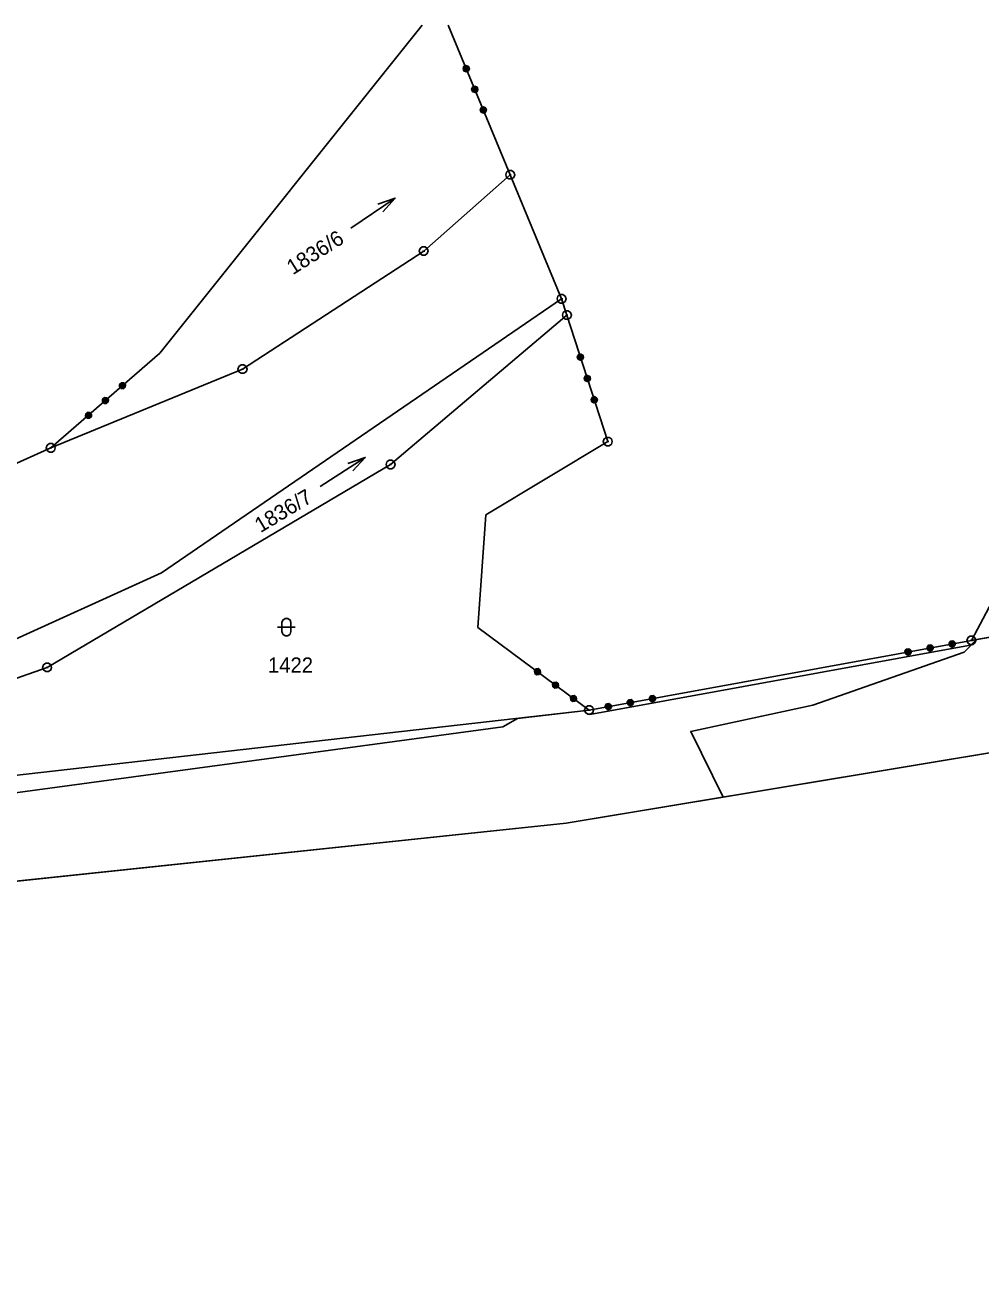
# Model space of a CAD drawing. Extents: x -779618 to -776429, y -1144546 to -1143350.
# Drawn here: x -778776.3 to -778669.3, y -1143491.2 to -1143349.7 of the extents above; entities that cross this region are included whole.
import ezdxf

# ---------------------------------------------------------------- set-up
doc = ezdxf.new("R2010")
doc.units = 0
for name, color, linetype in [('1', 7, 'Continuous'), ('11', 7, 'Continuous'), ('2', 7, 'Continuous'), ('3', 7, 'Continuous'), ('4', 7, 'Continuous'), ('8', 7, 'Continuous')]:
    doc.layers.add(name, color=color, linetype=linetype)

msp = doc.modelspace()

# ---------------------------------------------------------------- linework, layer by layer
at = {"layer": '1'}
for p, q in [((-778731.85, -1143349.66), (-778761.21, -1143386.36)), ((-778728.92, -1143349.66), (-778721.98, -1143366.4)), ((-778731.67, -1143374.93), (-778721.98, -1143366.4)), ((-778716.22, -1143380.29), (-778721.98, -1143366.4)), ((-778751.96, -1143388.16), (-778731.67, -1143374.93)), ((-778716.22, -1143380.29), (-778761.03, -1143410.96)), ((-778715.63, -1143382.11), (-778716.22, -1143380.29)), ((-778735.38, -1143398.84), (-778715.63, -1143382.11)), ((-778715.63, -1143382.11), (-778711.05, -1143396.27)), ((-778773.43, -1143396.97), (-778761.21, -1143386.36)), ((-778773.43, -1143396.97), (-778751.96, -1143388.16)), ((-778724.72, -1143404.47), (-778711.05, -1143396.27)), ((-778773.43, -1143396.97), (-778780.4, -1143400.1)), ((-778773.85, -1143421.55), (-778735.38, -1143398.84)), ((-778725.59, -1143417.09), (-778724.72, -1143404.47)), ((-778592.85, -1143405), (-778670.33, -1143418.53)), ((-778664.27, -1143407.08), (-778670.33, -1143418.53)), ((-778761.03, -1143410.96), (-778822.71, -1143438.81)), ((-778713.14, -1143426.33), (-778725.59, -1143417.09)), ((-778715.72, -1143438.98), (-778589.94, -1143418.07)), ((-778670.33, -1143418.53), (-778713.14, -1143426.33)), ((-778822.71, -1143438.81), (-778773.85, -1143421.55)), ((-778822.71, -1143438.81), (-778713.14, -1143426.33)), ((-778818.52, -1143449.84), (-778715.72, -1143438.98))]:
    msp.add_line(p, q, dxfattribs=at)
for points in [[(-778726.56, -1143354.51), (-778726.66, -1143354.76), (-778726.91, -1143354.86), (-778727.16, -1143354.76), (-778727.26, -1143354.51), (-778727.16, -1143354.26), (-778726.91, -1143354.16), (-778726.66, -1143354.26), (-778726.56, -1143354.51), (-778726.59, -1143354.53), (-778726.69, -1143354.31), (-778726.79, -1143354.27), (-778726.64, -1143354.64), (-778726.69, -1143354.72), (-778726.9, -1143354.22), (-778726.97, -1143354.25), (-778726.77, -1143354.74), (-778726.84, -1143354.78), (-778727.04, -1143354.29), (-778727.11, -1143354.33), (-778726.91, -1143354.81), (-778727, -1143354.8), (-778727.17, -1143354.4), (-778727.21, -1143354.5), (-778727.11, -1143354.76)], [(-778725.6, -1143356.83), (-778725.7, -1143357.08), (-778725.95, -1143357.18), (-778726.2, -1143357.08), (-778726.3, -1143356.83), (-778726.2, -1143356.58), (-778725.95, -1143356.47), (-778725.7, -1143356.58), (-778725.6, -1143356.83), (-778725.64, -1143356.83), (-778725.73, -1143356.61), (-778725.84, -1143356.57), (-778725.68, -1143356.94), (-778725.73, -1143357.04), (-778725.94, -1143356.52), (-778726.02, -1143356.56), (-778725.8, -1143357.07), (-778725.88, -1143357.1), (-778726.09, -1143356.59), (-778726.16, -1143356.62), (-778725.95, -1143357.13), (-778726.05, -1143357.09), (-778726.21, -1143356.72), (-778726.25, -1143356.83), (-778726.16, -1143357.05)], [(-778724.64, -1143359.15), (-778724.74, -1143359.39), (-778724.99, -1143359.5), (-778725.24, -1143359.39), (-778725.34, -1143359.15), (-778725.24, -1143358.9), (-778724.99, -1143358.79), (-778724.74, -1143358.9), (-778724.64, -1143359.15), (-778724.69, -1143359.12), (-778724.78, -1143358.9), (-778724.88, -1143358.88), (-778724.74, -1143359.23), (-778724.78, -1143359.33), (-778724.98, -1143358.85), (-778725.05, -1143358.88), (-778724.85, -1143359.36), (-778724.93, -1143359.39), (-778725.13, -1143358.91), (-778725.2, -1143358.94), (-778725, -1143359.42), (-778725.09, -1143359.41), (-778725.25, -1143359.03), (-778725.31, -1143359.11), (-778725.21, -1143359.33)], [(-778713.76, -1143386.84), (-778713.89, -1143387.08), (-778714.14, -1143387.16), (-778714.38, -1143387.04), (-778714.47, -1143386.78), (-778714.34, -1143386.54), (-778714.09, -1143386.46), (-778713.85, -1143386.58), (-778713.76, -1143386.84), (-778713.8, -1143386.86), (-778713.87, -1143386.63), (-778713.97, -1143386.58), (-778713.85, -1143386.96), (-778713.91, -1143387.04), (-778714.07, -1143386.53), (-778714.15, -1143386.55), (-778713.99, -1143387.06), (-778714.06, -1143387.09), (-778714.22, -1143386.59), (-778714.3, -1143386.61), (-778714.14, -1143387.11), (-778714.23, -1143387.09), (-778714.36, -1143386.68), (-778714.42, -1143386.77), (-778714.33, -1143387.04)], [(-778712.99, -1143389.22), (-778713.11, -1143389.46), (-778713.37, -1143389.55), (-778713.61, -1143389.42), (-778713.69, -1143389.17), (-778713.57, -1143388.93), (-778713.31, -1143388.85), (-778713.08, -1143388.97), (-778712.99, -1143389.22), (-778713.03, -1143389.23), (-778713.11, -1143389), (-778713.21, -1143388.95), (-778713.09, -1143389.33), (-778713.14, -1143389.43), (-778713.31, -1143388.9), (-778713.38, -1143388.92), (-778713.21, -1143389.45), (-778713.29, -1143389.48), (-778713.46, -1143388.95), (-778713.54, -1143388.97), (-778713.36, -1143389.5), (-778713.47, -1143389.45), (-778713.59, -1143389.07), (-778713.64, -1143389.17), (-778713.57, -1143389.4)], [(-778765.53, -1143389.69), (-778765.26, -1143389.7), (-778765.08, -1143389.91), (-778765.1, -1143390.18), (-778765.31, -1143390.35), (-778765.57, -1143390.33), (-778765.75, -1143390.13), (-778765.73, -1143389.86), (-778765.53, -1143389.69), (-778765.53, -1143389.74), (-778765.71, -1143389.9), (-778765.71, -1143390), (-778765.42, -1143389.75), (-778765.31, -1143389.76), (-778765.7, -1143390.1), (-778765.65, -1143390.16), (-778765.25, -1143389.82), (-778765.2, -1143389.88), (-778765.59, -1143390.22), (-778765.55, -1143390.29), (-778765.16, -1143389.95), (-778765.14, -1143390.03), (-778765.44, -1143390.3), (-778765.35, -1143390.33), (-778765.17, -1143390.17)], [(-778767.42, -1143391.33), (-778767.16, -1143391.35), (-778766.98, -1143391.55), (-778767, -1143391.82), (-778767.2, -1143392), (-778767.47, -1143391.98), (-778767.65, -1143391.78), (-778767.63, -1143391.51), (-778767.42, -1143391.33), (-778767.41, -1143391.37), (-778767.59, -1143391.53), (-778767.59, -1143391.64), (-778767.29, -1143391.38), (-778767.18, -1143391.38), (-778767.6, -1143391.75), (-778767.55, -1143391.81), (-778767.13, -1143391.44), (-778767.07, -1143391.51), (-778767.5, -1143391.87), (-778767.45, -1143391.93), (-778767.02, -1143391.57), (-778767.03, -1143391.68), (-778767.33, -1143391.94), (-778767.22, -1143391.95), (-778767.04, -1143391.79)], [(-778712.22, -1143391.61), (-778712.34, -1143391.85), (-778712.6, -1143391.94), (-778712.84, -1143391.81), (-778712.92, -1143391.56), (-778712.8, -1143391.32), (-778712.54, -1143391.23), (-778712.3, -1143391.36), (-778712.22, -1143391.61), (-778712.27, -1143391.59), (-778712.34, -1143391.36), (-778712.44, -1143391.33), (-778712.32, -1143391.69), (-778712.37, -1143391.79), (-778712.53, -1143391.29), (-778712.61, -1143391.32), (-778712.45, -1143391.81), (-778712.53, -1143391.84), (-778712.69, -1143391.34), (-778712.77, -1143391.36), (-778712.61, -1143391.85), (-778712.69, -1143391.84), (-778712.82, -1143391.45), (-778712.88, -1143391.52), (-778712.81, -1143391.75)], [(-778769.32, -1143392.98), (-778769.05, -1143393), (-778768.87, -1143393.2), (-778768.89, -1143393.47), (-778769.1, -1143393.65), (-778769.37, -1143393.63), (-778769.54, -1143393.42), (-778769.52, -1143393.15), (-778769.32, -1143392.98), (-778769.29, -1143393), (-778769.47, -1143393.16), (-778769.47, -1143393.27), (-778769.17, -1143393.01), (-778769.07, -1143393.03), (-778769.48, -1143393.38), (-778769.43, -1143393.44), (-778769.03, -1143393.1), (-778768.97, -1143393.15), (-778769.37, -1143393.5), (-778769.32, -1143393.56), (-778768.92, -1143393.21), (-778768.9, -1143393.3), (-778769.23, -1143393.59), (-778769.12, -1143393.6), (-778768.91, -1143393.42)], [(-778672.56, -1143419.26), (-778672.79, -1143419.11), (-778672.83, -1143418.84), (-778672.68, -1143418.62), (-778672.42, -1143418.57), (-778672.19, -1143418.73), (-778672.15, -1143418.99), (-778672.3, -1143419.21), (-778672.56, -1143419.26), (-778672.58, -1143419.22), (-778672.35, -1143419.18), (-778672.28, -1143419.09), (-778672.67, -1143419.16), (-778672.75, -1143419.09), (-778672.22, -1143419), (-778672.23, -1143418.92), (-778672.75, -1143419.01), (-778672.78, -1143418.93), (-778672.26, -1143418.84), (-778672.27, -1143418.76), (-778672.79, -1143418.86), (-778672.76, -1143418.77), (-778672.33, -1143418.69), (-778672.42, -1143418.63), (-778672.69, -1143418.68)], [(-778677.5, -1143420.16), (-778677.72, -1143420.01), (-778677.77, -1143419.74), (-778677.62, -1143419.52), (-778677.35, -1143419.47), (-778677.13, -1143419.63), (-778677.09, -1143419.89), (-778677.24, -1143420.11), (-778677.5, -1143420.16), (-778677.47, -1143420.12), (-778677.24, -1143420.07), (-778677.19, -1143419.98), (-778677.56, -1143420.05), (-778677.66, -1143419.99), (-778677.15, -1143419.89), (-778677.16, -1143419.82), (-778677.67, -1143419.91), (-778677.69, -1143419.83), (-778677.17, -1143419.74), (-778677.18, -1143419.66), (-778677.69, -1143419.75), (-778677.67, -1143419.66), (-778677.26, -1143419.59), (-778677.33, -1143419.52), (-778677.56, -1143419.56)], [(-778675.03, -1143419.71), (-778675.26, -1143419.56), (-778675.3, -1143419.29), (-778675.15, -1143419.07), (-778674.89, -1143419.02), (-778674.66, -1143419.18), (-778674.62, -1143419.44), (-778674.77, -1143419.66), (-778675.03, -1143419.71), (-778675.03, -1143419.67), (-778674.8, -1143419.63), (-778674.73, -1143419.54), (-778675.12, -1143419.61), (-778675.22, -1143419.54), (-778674.67, -1143419.44), (-778674.68, -1143419.36), (-778675.23, -1143419.46), (-778675.25, -1143419.39), (-778674.7, -1143419.28), (-778674.71, -1143419.21), (-778675.26, -1143419.31), (-778675.2, -1143419.21), (-778674.8, -1143419.14), (-778674.9, -1143419.08), (-778675.13, -1143419.12)], [(-778719.23, -1143422.21), (-778719.27, -1143421.94), (-778719.11, -1143421.72), (-778718.85, -1143421.68), (-778718.63, -1143421.85), (-778718.59, -1143422.11), (-778718.75, -1143422.33), (-778719.02, -1143422.37), (-778719.23, -1143422.21), (-778719.18, -1143422.2), (-778718.98, -1143422.34), (-778718.89, -1143422.31), (-778719.19, -1143422.09), (-778719.21, -1143421.97), (-778718.79, -1143422.28), (-778718.74, -1143422.22), (-778719.16, -1143421.91), (-778719.11, -1143421.85), (-778718.7, -1143422.16), (-778718.64, -1143422.1), (-778719.06, -1143421.79), (-778718.98, -1143421.75), (-778718.65, -1143421.99), (-778718.64, -1143421.9), (-778718.83, -1143421.75)], [(-778717.22, -1143423.7), (-778717.26, -1143423.44), (-778717.1, -1143423.22), (-778716.83, -1143423.18), (-778716.61, -1143423.34), (-778716.57, -1143423.61), (-778716.73, -1143423.82), (-778717, -1143423.86), (-778717.22, -1143423.7), (-778717.19, -1143423.68), (-778716.99, -1143423.82), (-778716.88, -1143423.8), (-778717.2, -1143423.56), (-778717.22, -1143423.45), (-778716.77, -1143423.79), (-778716.72, -1143423.72), (-778717.17, -1143423.39), (-778717.12, -1143423.32), (-778716.67, -1143423.66), (-778716.63, -1143423.59), (-778717.08, -1143423.26), (-778716.96, -1143423.24), (-778716.64, -1143423.48), (-778716.66, -1143423.37), (-778716.85, -1143423.23)], [(-778715.2, -1143425.2), (-778715.24, -1143424.93), (-778715.08, -1143424.72), (-778714.81, -1143424.68), (-778714.6, -1143424.84), (-778714.56, -1143425.1), (-778714.72, -1143425.32), (-778714.99, -1143425.36), (-778715.2, -1143425.2), (-778715.19, -1143425.16), (-778714.99, -1143425.3), (-778714.88, -1143425.29), (-778715.2, -1143425.05), (-778715.2, -1143424.95), (-778714.77, -1143425.27), (-778714.72, -1143425.21), (-778715.15, -1143424.89), (-778715.11, -1143424.82), (-778714.68, -1143425.14), (-778714.63, -1143425.07), (-778715.06, -1143424.76), (-778714.97, -1143424.72), (-778714.63, -1143424.98), (-778714.64, -1143424.87), (-778714.86, -1143424.7)], [(-778711.07, -1143426.28), (-778711.29, -1143426.12), (-778711.34, -1143425.86), (-778711.18, -1143425.64), (-778710.92, -1143425.59), (-778710.7, -1143425.74), (-778710.65, -1143426.01), (-778710.8, -1143426.23), (-778711.07, -1143426.28), (-778711.03, -1143426.23), (-778710.8, -1143426.19), (-778710.75, -1143426.1), (-778711.13, -1143426.17), (-778711.22, -1143426.1), (-778710.71, -1143426.01), (-778710.72, -1143425.93), (-778711.23, -1143426.02), (-778711.25, -1143425.95), (-778710.74, -1143425.85), (-778710.74, -1143425.77), (-778711.25, -1143425.86), (-778711.23, -1143425.78), (-778710.82, -1143425.71), (-778710.89, -1143425.64), (-778711.12, -1143425.68)], [(-778708.6, -1143425.83), (-778708.82, -1143425.67), (-778708.87, -1143425.41), (-778708.71, -1143425.19), (-778708.45, -1143425.14), (-778708.23, -1143425.29), (-778708.18, -1143425.56), (-778708.33, -1143425.78), (-778708.6, -1143425.83), (-778708.59, -1143425.79), (-778708.36, -1143425.74), (-778708.29, -1143425.65), (-778708.69, -1143425.72), (-778708.78, -1143425.66), (-778708.23, -1143425.56), (-778708.24, -1143425.48), (-778708.79, -1143425.58), (-778708.81, -1143425.5), (-778708.26, -1143425.4), (-778708.27, -1143425.32), (-778708.82, -1143425.42), (-778708.76, -1143425.33), (-778708.37, -1143425.26), (-778708.46, -1143425.19), (-778708.69, -1143425.24)], [(-778706.13, -1143425.38), (-778706.35, -1143425.22), (-778706.4, -1143424.96), (-778706.24, -1143424.74), (-778705.98, -1143424.69), (-778705.76, -1143424.84), (-778705.71, -1143425.11), (-778705.86, -1143425.33), (-778706.13, -1143425.38), (-778706.14, -1143425.34), (-778705.91, -1143425.3), (-778705.84, -1143425.2), (-778706.24, -1143425.28), (-778706.31, -1143425.21), (-778705.78, -1143425.11), (-778705.79, -1143425.03), (-778706.32, -1143425.13), (-778706.34, -1143425.05), (-778705.82, -1143424.95), (-778705.83, -1143424.88), (-778706.35, -1143424.97), (-778706.32, -1143424.88), (-778705.9, -1143424.81), (-778705.98, -1143424.74), (-778706.25, -1143424.79)]]:
    msp.add_lwpolyline(points, dxfattribs=at)
at = {"layer": '11'}
for p, q in [((-778713.14, -1143426.33), (-778670.33, -1143418.53)), ((-778670.33, -1143418.53), (-778669.74, -1143418.43))]:
    msp.add_line(p, q, dxfattribs=at)
for points in [[(-778654.99, -1143388.21), (-778601.22, -1143389.03), (-778529.9, -1143390.12), (-778475.97, -1143403.25), (-778476.13, -1143420.57), (-778501.66, -1143410.47), (-778538.84, -1143404.75), (-778592.85, -1143405), (-778669.74, -1143418.43)], [(-778698.13, -1143436.06), (-778701.77, -1143428.71), (-778688.08, -1143425.78), (-778671.14, -1143419.83), (-778669.74, -1143418.43)], [(-778391.62, -1143606.39), (-778385.54, -1143593.64), (-778391.52, -1143569.91), (-778391.96, -1143568.16), (-778423.5, -1143521.47), (-778427.52, -1143515.51), (-778428.85, -1143497.7), (-778426.9, -1143499.73), (-778427, -1143498.81), (-778429.76, -1143496.2), (-778458.56, -1143448.73), (-778464.32, -1143442.75), (-778464.56, -1143442.31), (-778464.82, -1143442.22), (-778468.65, -1143438.25), (-778504.96, -1143426.73), (-778540.55, -1143418.42), (-778589.94, -1143418.07), (-778698.13, -1143436.06)], [(-779127.81, -1143586.82), (-779123.49, -1143583.03), (-778998.42, -1143521.62), (-778865.4, -1143457.75), (-778880.7, -1143461.44), (-778864.23, -1143454.32), (-778822.71, -1143438.81), (-778812.34, -1143437.63), (-778812.03, -1143439.16), (-778787.11, -1143436.89), (-778722.82, -1143428.2), (-778721.18, -1143427.25), (-778713.14, -1143426.33)], [(-779126.05, -1143590.02), (-779014.28, -1143536.05), (-778904.07, -1143484.54), (-778858.15, -1143464.42), (-778818.52, -1143449.84), (-778715.72, -1143438.98), (-778698.13, -1143436.06)]]:
    msp.add_lwpolyline(points, dxfattribs=at)
at = {"layer": '3'}
for p, q in [((-778739.84, -1143372.36), (-778734.88, -1143369)), ((-778743.25, -1143401.28), (-778738.21, -1143398.04))]:
    msp.add_line(p, q, dxfattribs=at)
for points in [[(-778736.81, -1143369.7), (-778734.88, -1143369), (-778736.25, -1143370.53)], [(-778740.16, -1143398.7), (-778738.21, -1143398.04), (-778739.62, -1143399.54)], [(-778748.05, -1143417.03), (-778746.78, -1143417.03), (-778746.05, -1143417.03)]]:
    msp.add_lwpolyline(points, dxfattribs=at)
msp.add_lwpolyline([(-778747.55, -1143416.53), (-778747.45, -1143416.24), (-778747.2, -1143416.06), (-778746.89, -1143416.06), (-778746.64, -1143416.24), (-778746.54, -1143416.53), (-778746.54, -1143417.53), (-778746.64, -1143417.82), (-778746.89, -1143418), (-778747.2, -1143418), (-778747.45, -1143417.82), (-778747.55, -1143417.53)], close=True, dxfattribs=at)
at = {"layer": '4'}
msp.add_line((-778670.24, -1143419.02), (-778713.05, -1143426.82), dxfattribs=at)
at = {"layer": '8'}
for p, q in [((-778722.1, -1143366.4), (-778721.86, -1143366.4)), ((-778731.79, -1143374.93), (-778731.55, -1143374.93)), ((-778716.34, -1143380.29), (-778716.1, -1143380.29)), ((-778715.75, -1143382.11), (-778715.51, -1143382.11)), ((-778752.08, -1143388.16), (-778751.84, -1143388.16)), ((-778711.17, -1143396.27), (-778710.93, -1143396.27)), ((-778773.55, -1143396.97), (-778773.31, -1143396.97)), ((-778735.5, -1143398.84), (-778735.26, -1143398.84)), ((-778670.45, -1143418.53), (-778670.21, -1143418.53)), ((-778773.97, -1143421.55), (-778773.73, -1143421.55)), ((-778713.26, -1143426.33), (-778713.02, -1143426.33))]:
    msp.add_line(p, q, dxfattribs=at)
for points in [[(-778721.83, -1143365.92), (-778721.58, -1143366.1), (-778721.48, -1143366.39), (-778721.58, -1143366.68), (-778721.83, -1143366.86), (-778722.14, -1143366.86), (-778722.39, -1143366.68), (-778722.49, -1143366.39), (-778722.39, -1143366.1), (-778722.14, -1143365.92)], [(-778731.52, -1143374.45), (-778731.27, -1143374.63), (-778731.17, -1143374.92), (-778731.27, -1143375.21), (-778731.52, -1143375.39), (-778731.83, -1143375.39), (-778732.08, -1143375.21), (-778732.18, -1143374.92), (-778732.08, -1143374.63), (-778731.83, -1143374.45)], [(-778716.07, -1143379.81), (-778715.82, -1143379.99), (-778715.72, -1143380.28), (-778715.82, -1143380.57), (-778716.07, -1143380.75), (-778716.38, -1143380.75), (-778716.63, -1143380.57), (-778716.73, -1143380.28), (-778716.63, -1143379.99), (-778716.38, -1143379.81)], [(-778715.48, -1143381.63), (-778715.23, -1143381.81), (-778715.13, -1143382.1), (-778715.23, -1143382.39), (-778715.48, -1143382.57), (-778715.79, -1143382.57), (-778716.04, -1143382.39), (-778716.14, -1143382.1), (-778716.04, -1143381.81), (-778715.79, -1143381.63)], [(-778751.81, -1143387.68), (-778751.56, -1143387.86), (-778751.46, -1143388.15), (-778751.56, -1143388.44), (-778751.81, -1143388.62), (-778752.12, -1143388.62), (-778752.37, -1143388.44), (-778752.47, -1143388.15), (-778752.37, -1143387.86), (-778752.12, -1143387.68)], [(-778710.9, -1143395.79), (-778710.65, -1143395.97), (-778710.55, -1143396.26), (-778710.65, -1143396.55), (-778710.9, -1143396.73), (-778711.21, -1143396.73), (-778711.46, -1143396.55), (-778711.56, -1143396.26), (-778711.46, -1143395.97), (-778711.21, -1143395.79)], [(-778773.28, -1143396.49), (-778773.03, -1143396.67), (-778772.93, -1143396.96), (-778773.03, -1143397.25), (-778773.28, -1143397.43), (-778773.59, -1143397.43), (-778773.84, -1143397.25), (-778773.94, -1143396.96), (-778773.84, -1143396.67), (-778773.59, -1143396.49)], [(-778735.23, -1143398.36), (-778734.98, -1143398.54), (-778734.88, -1143398.83), (-778734.98, -1143399.12), (-778735.23, -1143399.3), (-778735.54, -1143399.3), (-778735.79, -1143399.12), (-778735.89, -1143398.83), (-778735.79, -1143398.54), (-778735.54, -1143398.36)], [(-778670.18, -1143418.05), (-778669.93, -1143418.23), (-778669.83, -1143418.52), (-778669.93, -1143418.81), (-778670.18, -1143418.99), (-778670.49, -1143418.99), (-778670.74, -1143418.81), (-778670.84, -1143418.52), (-778670.74, -1143418.23), (-778670.49, -1143418.05)], [(-778773.7, -1143421.07), (-778773.45, -1143421.25), (-778773.35, -1143421.54), (-778773.45, -1143421.83), (-778773.7, -1143422.01), (-778774.01, -1143422.01), (-778774.26, -1143421.83), (-778774.36, -1143421.54), (-778774.26, -1143421.25), (-778774.01, -1143421.07)], [(-778712.99, -1143425.85), (-778712.74, -1143426.03), (-778712.64, -1143426.32), (-778712.74, -1143426.61), (-778712.99, -1143426.79), (-778713.3, -1143426.79), (-778713.55, -1143426.61), (-778713.65, -1143426.32), (-778713.55, -1143426.03), (-778713.3, -1143425.85)]]:
    msp.add_lwpolyline(points, close=True, dxfattribs=at)

# ---------------------------------------------------------------- texts
at = {"layer": '2'}
for s, rotation, p in [('1836/6', 32.2002, (-778746.33, -1143377.65)), ('1836/7', 30.997, (-778749.95, -1143406.52))]:
    msp.add_text(s, height=1.7, rotation=rotation, dxfattribs=at).set_placement(p)
msp.add_text('1422', height=1.7, dxfattribs=at).set_placement((-778749.12, -1143422.13))

doc.saveas('drawing.dxf')
